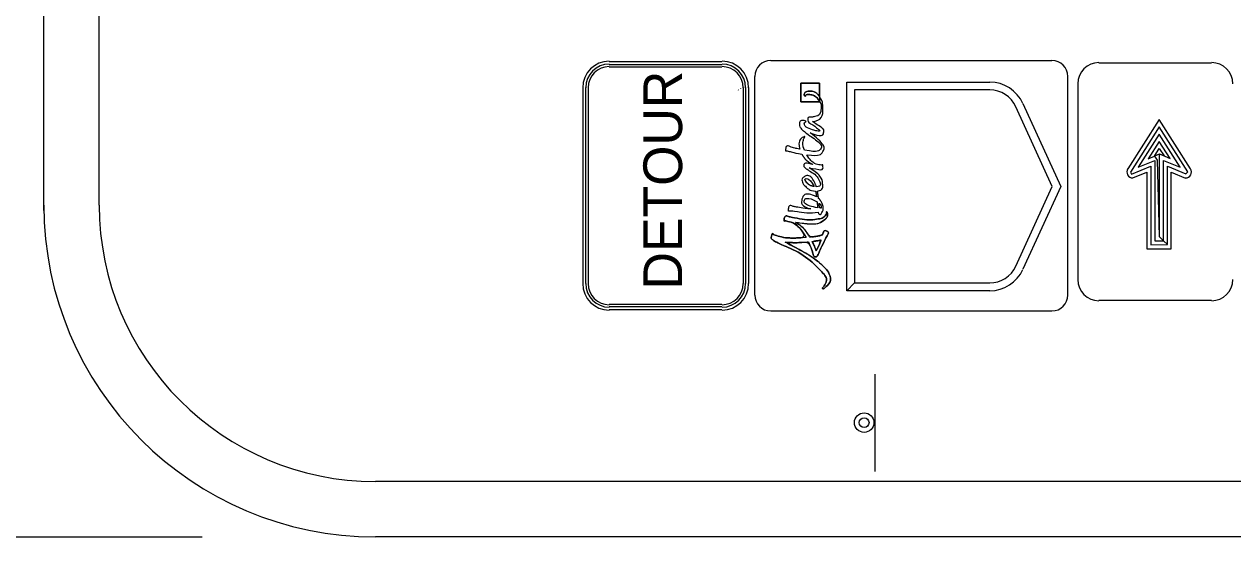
# Model space of a CAD drawing. Extents: x 1806 to 2022, y 110 to 389.
# Drawn here: x 1888.17 to 1914.62, y 289.03 to 300.26 of the extents above; entities that cross this region are included whole.
import ezdxf

# ---------------------------------------------------------------- set-up
doc = ezdxf.new("R2010")
doc.units = 0
for name, color, linetype in [('Level 10', 7, 'Continuous'), ('Level 2', 7, 'Continuous'), ('Level 44', 7, 'Continuous'), ('Level 53', 7, 'Continuous')]:
    doc.layers.add(name, color=color, linetype=linetype)

msp = doc.modelspace()

# ---------------------------------------------------------------- linework, layer by layer
at = {"layer": 'Level 10'}
for p, q in [((1888.603, 296.177), (1888.603, 355.206)), ((1889.812, 296.293), (1889.812, 355.206)), ((1957.331, 290.244), (1895.86, 290.244)), ((1874.503, 289.035), (1892.067, 289.035)), ((1957.331, 289.035), (1895.86, 289.035))]:
    msp.add_line(p, q, dxfattribs=at)
for radius in [7.258, 6.048]:
    msp.add_arc((1895.86, 296.293), radius, 180, 270, dxfattribs=at)
at = {"layer": 'Level 2'}
for p, q in [((1904.507, 299.458), (1910.662, 299.458)), ((1904.16, 294.326), (1904.16, 299.111)), ((1904.16, 294.326), (1904.16, 299.111)), ((1906.173, 294.421), (1906.173, 298.987)), ((1906.173, 298.987), (1909.3, 298.987)), ((1911.009, 294.326), (1911.009, 299.111)), ((1909.3, 298.816), (1906.344, 298.816)), ((1906.344, 298.816), (1906.344, 294.593)), ((1910.664, 296.704), (1909.871, 298.448)), ((1910.027, 298.519), (1910.853, 296.704)), ((1909.871, 294.96), (1910.664, 296.704)), ((1910.853, 296.704), (1910.027, 294.89)), ((1906.173, 294.421), (1906.344, 294.593)), ((1906.344, 294.593), (1906.173, 294.421)), ((1909.3, 294.421), (1906.173, 294.421)), ((1906.344, 294.593), (1909.3, 294.593)), ((1904.507, 293.979), (1910.662, 293.979))]:
    msp.add_line(p, q, dxfattribs=at)
for centre, radius, start, end in [((1904.507, 299.111), 0.347, 90, 180), ((1910.662, 299.111), 0.347, 360, 90), ((1909.3, 298.188), 0.799, 24.4568, 90), ((1909.3, 298.188), 0.628, 24.4568, 90), ((1909.3, 295.22), 0.628, 270, 335.5432), ((1909.3, 295.22), 0.799, 270, 335.5432), ((1904.507, 294.326), 0.347, 180, 270), ((1910.662, 294.326), 0.347, 270, 360)]:
    msp.add_arc(centre, radius, start, end, dxfattribs=at)
at = {"layer": 'Level 44'}
for p, q in [((1900.975, 299.44), (1903.44, 299.44)), ((1911.69, 299.408), (1914.155, 299.408)), ((1900.975, 299.375), (1903.44, 299.375)), ((1900.975, 299.321), (1903.44, 299.321)), ((1900.975, 299.321), (1903.44, 299.321)), ((1911.233, 294.665), (1911.233, 298.956)), ((1900.4, 294.578), (1900.4, 298.869)), ((1900.465, 294.578), (1900.465, 298.869)), ((1900.519, 294.578), (1900.519, 298.869)), ((1900.519, 294.578), (1900.519, 298.869)), ((1903.799, 298.812), (1903.797, 298.816)), ((1903.857, 298.841), (1903.855, 298.845)), ((1903.903, 298.869), (1903.903, 294.578)), ((1903.903, 298.869), (1903.903, 294.578)), ((1903.905, 298.865), (1903.903, 298.869)), ((1903.957, 298.869), (1903.957, 294.578)), ((1904.022, 298.869), (1904.022, 294.578)), ((1913.01, 298.167), (1912.323, 297.092)), ((1913.693, 297.092), (1913.01, 298.167)), ((1903.909, 296.944), (1903.909, 296.944)), ((1903.909, 296.944), (1903.909, 296.944)), ((1912.434, 296.891), (1912.741, 297.019)), ((1912.741, 297.019), (1912.741, 295.342)), ((1913.274, 297.019), (1913.582, 296.887)), ((1913.274, 295.342), (1913.274, 297.015)), ((1912.741, 295.342), (1913.274, 295.342)), ((1903.44, 294.122), (1900.975, 294.122)), ((1903.44, 294.122), (1900.975, 294.122)), ((1914.155, 294.209), (1911.69, 294.209)), ((1903.44, 294.068), (1900.975, 294.068)), ((1903.44, 294.003), (1900.975, 294.003)), ((1906.791, 290.464), (1906.791, 292.597))]:
    msp.add_line(p, q, dxfattribs=at)
for points in [[(1913.193, 295.432), (1913.193, 297.147), (1913.59, 296.977), (1913.633, 297.023), (1913.01, 298.009), (1912.378, 297.019), (1912.404, 296.972), (1912.826, 297.147), (1912.826, 295.428), (1913.193, 295.432), (1913.104, 295.513), (1913.104, 297.275), (1913.471, 297.126), (1913.01, 297.847), (1912.549, 297.126), (1912.916, 297.275), (1912.916, 295.513), (1913.104, 295.513), (1913.018, 295.603), (1913.018, 297.416), (1913.249, 297.318), (1913.01, 297.689), (1912.767, 297.309), (1912.903, 297.365), (1913.01, 297.535), (1913.117, 297.373), (1913.006, 297.407), (1912.903, 297.365), (1912.963, 297.279), (1913.006, 295.607), (1913.018, 295.603)], [(1913.193, 295.432), (1913.193, 297.147)]]:
    msp.add_lwpolyline(points, dxfattribs=at)
for radius in [0.213, 0.107]:
    msp.add_circle((1906.552, 291.535), radius, dxfattribs=at)
for centre, radius, start, end in [((1900.974, 298.865), 0.581, 90, 180), ((1903.443, 298.865), 0.581, 0, 90), ((1911.689, 298.952), 0.462, 90, 180), ((1914.158, 298.952), 0.462, 0, 90), ((1900.974, 298.865), 0.516, 90, 180), ((1900.974, 298.865), 0.462, 90, 180), ((1900.974, 298.865), 0.462, 90, 180), ((1903.443, 298.865), 0.516, 0, 90), ((1903.443, 298.865), 0.462, 0, 90), ((1903.443, 298.865), 0.462, 0, 90), ((1912.434, 297.023), 0.132, 147.5015, 269.8949), ((1913.583, 297.021), 0.132, 269.8942, 32.4962), ((1911.689, 294.665), 0.462, 180, 270), ((1914.158, 294.665), 0.462, 270, 360), ((1900.974, 294.578), 0.581, 180, 270), ((1900.974, 294.578), 0.516, 180, 270), ((1900.974, 294.578), 0.462, 180, 270), ((1900.974, 294.578), 0.462, 180, 270), ((1903.443, 294.578), 0.462, 270, 360), ((1903.443, 294.578), 0.581, 270, 360), ((1903.443, 294.578), 0.516, 270, 360), ((1903.443, 294.578), 0.462, 270, 360)]:
    msp.add_arc(centre, radius, start, end, dxfattribs=at)
at = {"layer": 'Level 53'}
msp.add_line((1905.577, 298.667), (1905.577, 298.567), dxfattribs=at)
msp.add_lwpolyline([(1905.577, 298.667), (1905.577, 298.962), (1905.17, 298.962), (1905.17, 298.555), (1905.577, 298.555), (1905.577, 298.567)], dxfattribs=at)
for points, degree in [([(1905.17, 298.555), (1905.17, 298.555), (1905.577, 298.555), (1905.577, 298.555), (1905.577, 298.555), (1905.577, 298.567), (1905.577, 298.567), (1905.524, 298.655), (1905.423, 298.714), (1905.34, 298.714), (1905.268, 298.714), (1905.272, 298.676), (1905.261, 298.68), (1905.233, 298.693), (1905.249, 298.783), (1905.351, 298.788), (1905.437, 298.792), (1905.52, 298.747), (1905.577, 298.667), (1905.577, 298.667), (1905.577, 298.962), (1905.577, 298.962), (1905.577, 298.962), (1905.17, 298.962), (1905.17, 298.962), (1905.17, 298.962), (1905.17, 298.555), (1905.17, 298.555)], 3), ([(1905.577, 298.567), (1905.524, 298.655), (1905.423, 298.714), (1905.34, 298.714), (1905.268, 298.714), (1905.272, 298.676), (1905.261, 298.68), (1905.233, 298.693), (1905.249, 298.783), (1905.351, 298.788), (1905.437, 298.792), (1905.52, 298.747), (1905.577, 298.667)], 3), ([(1905.422, 298.124), (1905.506, 298.134), (1905.651, 298.19), (1905.651, 298.415), (1905.651, 298.517), (1905.623, 298.603), (1905.577, 298.667)], 3), ([(1905.613, 298.441), (1905.613, 298.274), (1905.483, 298.23), (1905.419, 298.222), (1905.376, 298.217), (1905.315, 298.226), (1905.323, 298.152), (1905.329, 298.101), (1905.429, 298.054), (1905.514, 297.988), (1905.587, 297.932), (1905.58, 297.907), (1905.517, 297.92), (1905.439, 297.936), (1905.255, 298.002), (1905.242, 298.076), (1905.236, 298.111), (1905.297, 298.123), (1905.259, 298.139), (1905.221, 298.155), (1905.138, 298.14), (1905.138, 298.063), (1905.138, 298.009), (1905.196, 297.944), (1905.261, 297.891), (1905.318, 297.844), (1905.664, 297.61), (1905.589, 297.511), (1905.554, 297.465), (1905.412, 297.469), (1905.245, 297.498)], 3), ([(1905.577, 298.567), (1905.6, 298.529), (1905.613, 298.486), (1905.613, 298.441)], 2), ([(1905.373, 297.877), (1905.491, 297.825), (1905.642, 297.795), (1905.665, 297.874), (1905.692, 297.966), (1905.54, 298.039), (1905.422, 298.124)], 3), ([(1905.297, 297.396), (1905.455, 297.378), (1905.596, 297.384), (1905.641, 297.456), (1905.723, 297.588), (1905.506, 297.774), (1905.373, 297.877)], 3), ([(1905.144, 297.518), (1905.09, 297.529), (1905.034, 297.543), (1904.981, 297.558), (1904.932, 297.572), (1904.846, 297.612), (1904.83, 297.507), (1904.825, 297.474), (1904.841, 297.488), (1904.886, 297.477), (1904.97, 297.456), (1905.078, 297.431), (1905.187, 297.412)], 3), ([(1905.245, 297.498), (1905.2, 297.615), (1905.215, 297.712), (1905.241, 297.767), (1905.254, 297.794), (1905.252, 297.798), (1905.222, 297.786), (1905.178, 297.769), (1905.11, 297.675), (1905.141, 297.528), (1905.142, 297.525), (1905.143, 297.521), (1905.144, 297.518)], 3), ([(1905.187, 297.412), (1905.237, 297.326), (1905.32, 297.245), (1905.43, 297.186)], 2), ([(1905.349, 297.111), (1905.447, 297.101), (1905.661, 297.037), (1905.65, 297.146), (1905.646, 297.189), (1905.639, 297.17), (1905.602, 297.173), (1905.473, 297.182), (1905.364, 297.29), (1905.297, 297.396)], 3), ([(1905.43, 297.186), (1905.379, 297.196), (1905.323, 297.212), (1905.286, 297.213), (1905.246, 297.214), (1905.237, 297.187), (1905.234, 297.176), (1905.227, 297.153), (1905.239, 297.125), (1905.278, 297.098), (1905.369, 297.033), (1905.512, 296.952), (1905.573, 296.828), (1905.616, 296.739), (1905.572, 296.7), (1905.505, 296.697)], 3), ([(1905.528, 296.603), (1905.6, 296.611), (1905.655, 296.658), (1905.645, 296.767), (1905.63, 296.922), (1905.441, 297.059), (1905.349, 297.111)], 3), ([(1905.505, 296.697), (1905.5, 296.715), (1905.494, 296.731), (1905.489, 296.744), (1905.417, 296.905), (1905.309, 296.961), (1905.244, 296.92), (1905.181, 296.881), (1905.2, 296.77), (1905.293, 296.682), (1905.338, 296.639), (1905.417, 296.605), (1905.488, 296.601)], 3), ([(1905.301, 296.784), (1905.251, 296.838), (1905.254, 296.865), (1905.268, 296.872), (1905.297, 296.887), (1905.4, 296.823), (1905.456, 296.702)], 3), ([(1905.456, 296.702), (1905.401, 296.712), (1905.34, 296.741), (1905.301, 296.784)], 2), ([(1905.51, 296.474), (1905.387, 296.549), (1905.22, 296.543), (1905.193, 296.432), (1905.16, 296.303), (1905.285, 296.238), (1905.389, 296.211)], 3), ([(1905.488, 296.601), (1905.496, 296.564), (1905.503, 296.521), (1905.51, 296.474)], 2), ([(1905.554, 296.441), (1905.547, 296.494), (1905.539, 296.551), (1905.528, 296.603)], 2), ([(1905.389, 296.211), (1905.285, 296.219), (1905.158, 296.236), (1905.041, 296.259), (1904.992, 296.269), (1904.907, 296.303), (1904.89, 296.196), (1904.885, 296.162), (1904.901, 296.168), (1904.947, 296.17), (1905.008, 296.174), (1905.381, 296.106), (1905.544, 296.142)], 3), ([(1905.533, 296.238), (1905.402, 296.256), (1905.221, 296.324), (1905.25, 296.408), (1905.267, 296.457), (1905.42, 296.432), (1905.522, 296.369)], 3), ([(1905.522, 296.369), (1905.526, 296.328), (1905.53, 296.284), (1905.533, 296.238)], 2), ([(1905.544, 296.142), (1905.559, 296.096), (1905.594, 296.077), (1905.63, 296.136), (1905.655, 296.177), (1905.664, 296.266), (1905.619, 296.357), (1905.603, 296.389), (1905.581, 296.417), (1905.554, 296.441)], 3), ([(1905.574, 296.235), (1905.573, 296.258), (1905.57, 296.294), (1905.566, 296.336)], 2), ([(1905.566, 296.336), (1905.59, 296.314), (1905.608, 296.289), (1905.612, 296.262)], 2), ([(1905.612, 296.225), (1905.607, 296.231), (1905.6, 296.234), (1905.591, 296.234), (1905.585, 296.234), (1905.58, 296.234), (1905.574, 296.235)], 3), ([(1905.612, 296.262), (1905.614, 296.247), (1905.614, 296.234), (1905.612, 296.225)], 2), ([(1905.725, 296.113), (1905.719, 296.069), (1905.659, 296.012), (1905.561, 295.994), (1905.384, 295.963), (1905.21, 295.982), (1904.951, 296.034), (1904.902, 296.043), (1904.816, 296.077), (1904.8, 295.97), (1904.795, 295.936), (1904.812, 295.954), (1904.856, 295.944), (1905.05, 295.904), (1905.189, 295.745), (1905.282, 295.587), (1905.061, 295.57), (1904.815, 295.577), (1904.665, 295.619), (1904.538, 295.654), (1904.561, 295.696), (1904.534, 295.644), (1904.506, 295.589), (1904.543, 295.53), (1904.638, 295.483), (1904.733, 295.436), (1905.247, 295.217), (1905.594, 294.868), (1905.772, 294.689), (1905.68, 294.528), (1905.653, 294.495), (1905.631, 294.469), (1905.665, 294.459), (1905.7, 294.492), (1905.856, 294.636), (1905.767, 294.848), (1905.69, 294.924), (1905.477, 295.137), (1905.02, 295.384), (1904.827, 295.484), (1904.936, 295.474), (1905.119, 295.471), (1905.333, 295.492), (1905.386, 295.383), (1905.417, 295.287), (1905.429, 295.241), (1905.442, 295.191), (1905.462, 295.161), (1905.485, 295.16), (1905.51, 295.159), (1905.531, 295.192), (1905.554, 295.24), (1905.595, 295.326), (1905.713, 295.576), (1905.749, 295.638), (1905.78, 295.691), (1905.756, 295.717), (1905.723, 295.732), (1905.68, 295.753), (1905.655, 295.697), (1905.638, 295.642), (1905.566, 295.621), (1905.468, 295.605), (1905.36, 295.594), (1905.282, 295.721), (1905.177, 295.846), (1905.047, 295.919), (1905.156, 295.9), (1905.527, 295.854), (1905.684, 295.971), (1905.718, 295.997), (1905.756, 296.054), (1905.75, 296.109), (1905.748, 296.135), (1905.731, 296.149), (1905.725, 296.146), (1905.72, 296.143), (1905.727, 296.128), (1905.725, 296.113)], 3), ([(1905.725, 296.113), (1905.719, 296.069), (1905.659, 296.012), (1905.561, 295.994), (1905.384, 295.963), (1905.21, 295.982), (1904.951, 296.034), (1904.902, 296.043), (1904.816, 296.077), (1904.8, 295.97), (1904.795, 295.936), (1904.812, 295.954), (1904.856, 295.944), (1905.05, 295.904), (1905.189, 295.745), (1905.282, 295.587)], 3), ([(1905.047, 295.919), (1905.156, 295.9), (1905.527, 295.854), (1905.684, 295.971), (1905.718, 295.997), (1905.756, 296.054), (1905.75, 296.109), (1905.748, 296.135), (1905.731, 296.149), (1905.725, 296.146), (1905.72, 296.143), (1905.727, 296.128), (1905.725, 296.113)], 3), ([(1905.36, 295.594), (1905.282, 295.721), (1905.177, 295.846), (1905.047, 295.919)], 2), ([(1905.333, 295.492), (1905.386, 295.383), (1905.417, 295.287), (1905.429, 295.241), (1905.442, 295.191), (1905.462, 295.161), (1905.485, 295.16), (1905.51, 295.159), (1905.531, 295.192), (1905.554, 295.24), (1905.595, 295.326), (1905.713, 295.576), (1905.749, 295.638), (1905.78, 295.691), (1905.756, 295.717), (1905.723, 295.732), (1905.68, 295.753), (1905.655, 295.697), (1905.638, 295.642)], 3), ([(1905.282, 295.587), (1905.061, 295.57), (1904.815, 295.577), (1904.665, 295.619), (1904.538, 295.654), (1904.561, 295.696), (1904.534, 295.644), (1904.506, 295.589), (1904.543, 295.53), (1904.638, 295.483), (1904.733, 295.436), (1905.247, 295.217), (1905.594, 294.868), (1905.772, 294.689), (1905.68, 294.528), (1905.653, 294.495), (1905.631, 294.469), (1905.665, 294.459), (1905.7, 294.492), (1905.856, 294.636), (1905.767, 294.848), (1905.69, 294.924), (1905.477, 295.137), (1905.02, 295.384), (1904.827, 295.484)], 3), ([(1904.827, 295.484), (1904.936, 295.474), (1905.119, 295.471), (1905.333, 295.492)], 2), ([(1905.638, 295.642), (1905.566, 295.621), (1905.468, 295.605), (1905.36, 295.594)], 2), ([(1905.413, 295.5), (1905.5, 295.51), (1905.562, 295.521), (1905.609, 295.534)], 2), ([(1905.504, 295.296), (1905.483, 295.353), (1905.453, 295.424), (1905.413, 295.5)], 2), ([(1905.504, 295.296), (1905.483, 295.353), (1905.453, 295.424), (1905.413, 295.5), (1905.5, 295.51), (1905.562, 295.521), (1905.609, 295.534), (1905.589, 295.478), (1905.556, 295.399), (1905.504, 295.296)], 3), ([(1905.609, 295.534), (1905.589, 295.478), (1905.556, 295.399), (1905.504, 295.296)], 2)]:
    msp.add_open_spline(points, degree=degree, dxfattribs=at)

# ---------------------------------------------------------------- texts
at = {"layer": 'Level 44'}
msp.add_text('DETOUR', height=0.848, rotation=90, dxfattribs=at).set_placement((1902.569, 294.449))

doc.saveas('drawing.dxf')
